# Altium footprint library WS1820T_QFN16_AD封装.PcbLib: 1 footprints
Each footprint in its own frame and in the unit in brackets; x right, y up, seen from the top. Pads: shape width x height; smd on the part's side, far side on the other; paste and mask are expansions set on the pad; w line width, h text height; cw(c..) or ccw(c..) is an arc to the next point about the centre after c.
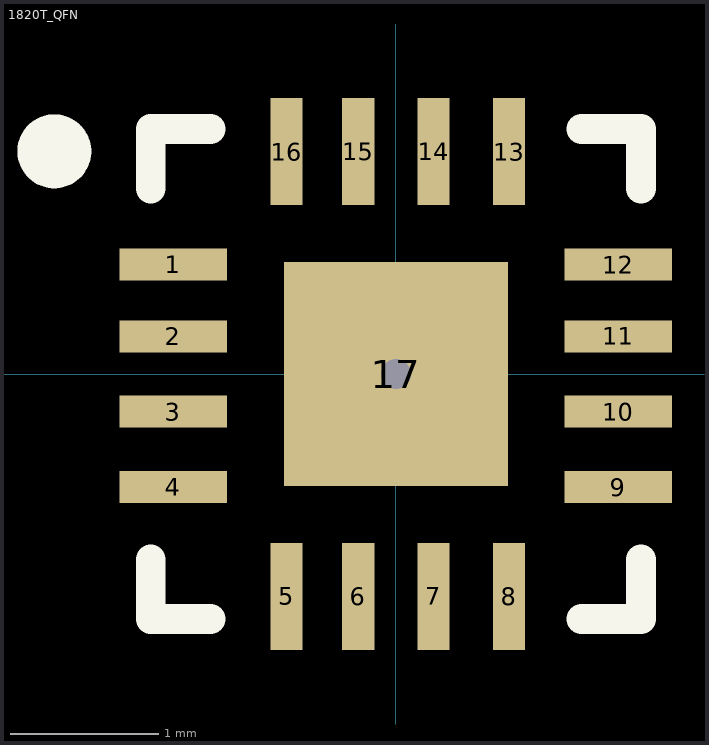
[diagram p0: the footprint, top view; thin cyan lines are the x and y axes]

## 1820T_QFN [mil]
pads (17):
  rect 28.5x8.5 smd paste+0 mask+2: 1(-59,29) 2(-59,10) 3(-59,-10) 4(-59,-30) 9(59,-30) 10(59,-10) 11(59,10) 12(59,29)
  rect 8.5x28.5 smd paste+0 mask+2: 5(-29,-59) 6(-10,-59) 7(10,-59) 8(30,-59) 13(30,59) 14(10,59) 15(-10,59) 16(-29,59)
  rect 59.5x59.5 smd paste+0 mask+2: 17(0,0)
via 0,0 diameter 19.7 hole 7.9
Top Overlay:
  lines w7.9: -65,-49.2 -65,-65 -49.2,-65 ; -65,49.2 -65,65 -49.2,65 ; 49.2,-65 65,-65 65,-49.2 ; 49.2,65 65,65 65,49.2
  lines w9.8: -85.7,59 cw(c-90.6,59.05) -85.7,59.1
